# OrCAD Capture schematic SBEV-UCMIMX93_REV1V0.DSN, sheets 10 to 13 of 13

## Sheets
10 05 Gbe PHY2: size B; title: SBEV-UCMIMX93   5. Gbe PHY2; note: 17 HaYetsira Street; note: Yokneam Illit, Israel 2069208
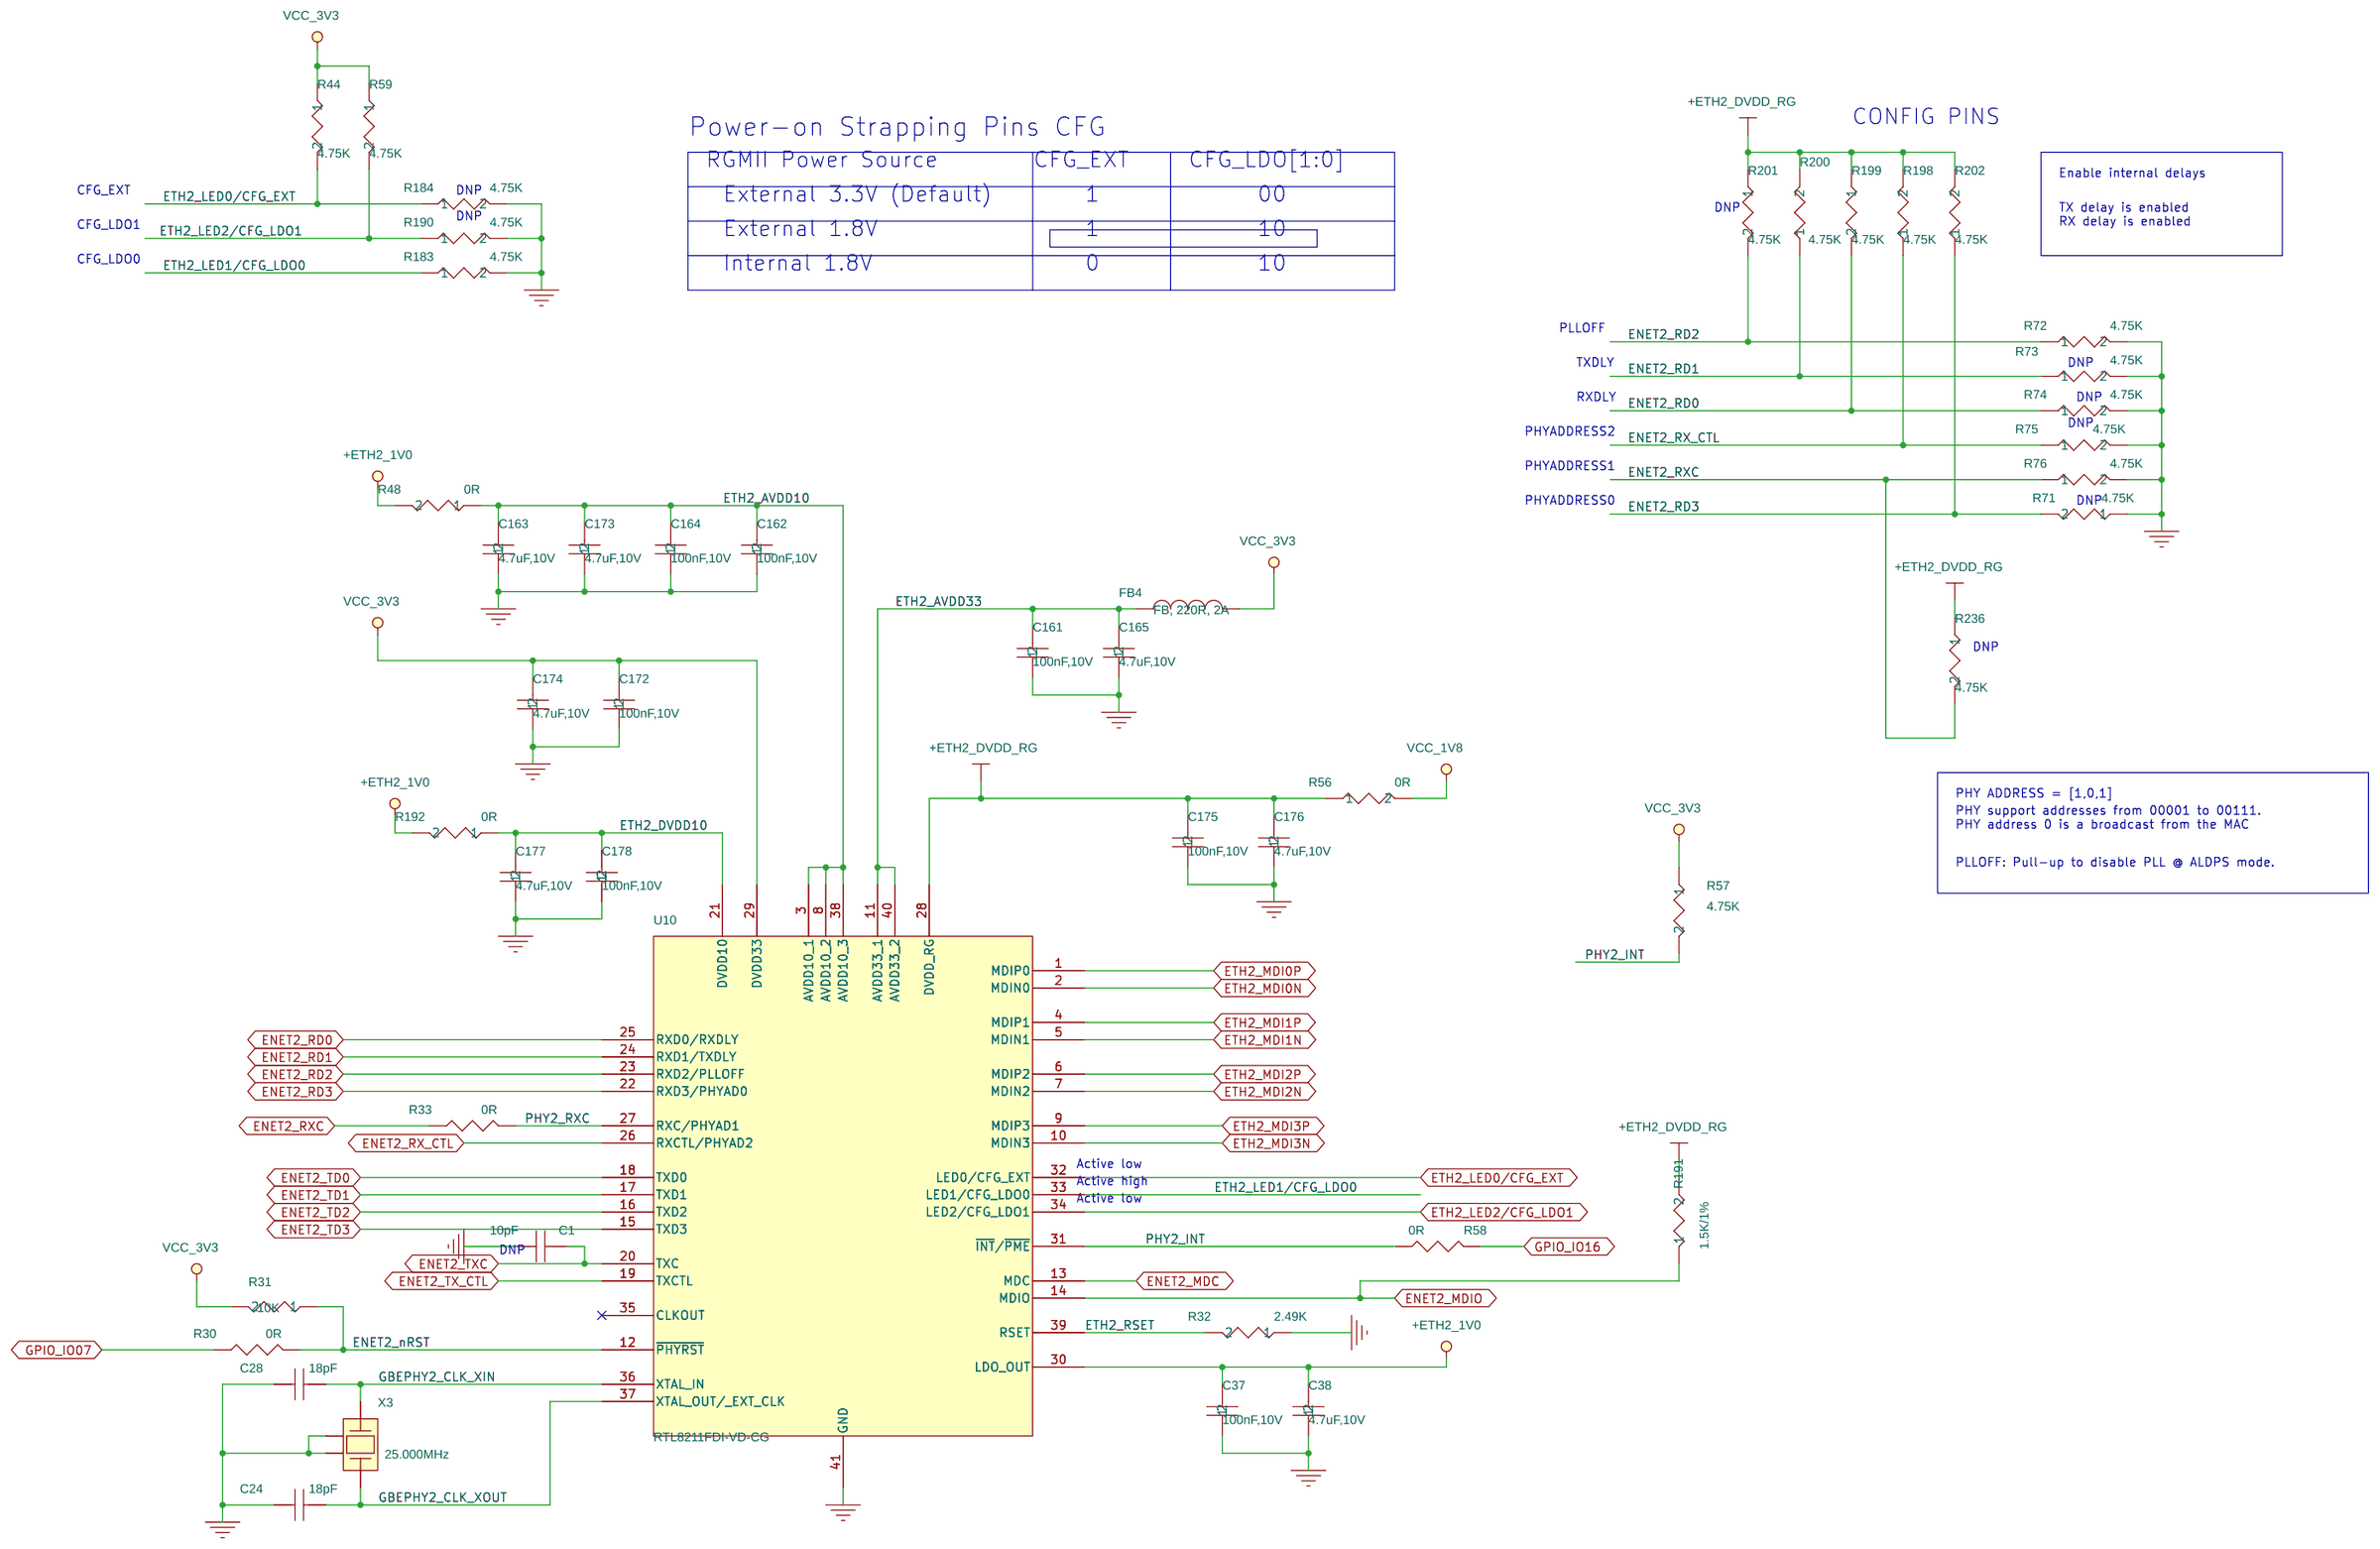
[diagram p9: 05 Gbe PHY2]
11 10 Console, SD, JTAG,miniPCI: size C; title: SBEV-UCMIMX93      10. Console, RS232, SD, miniPCIe
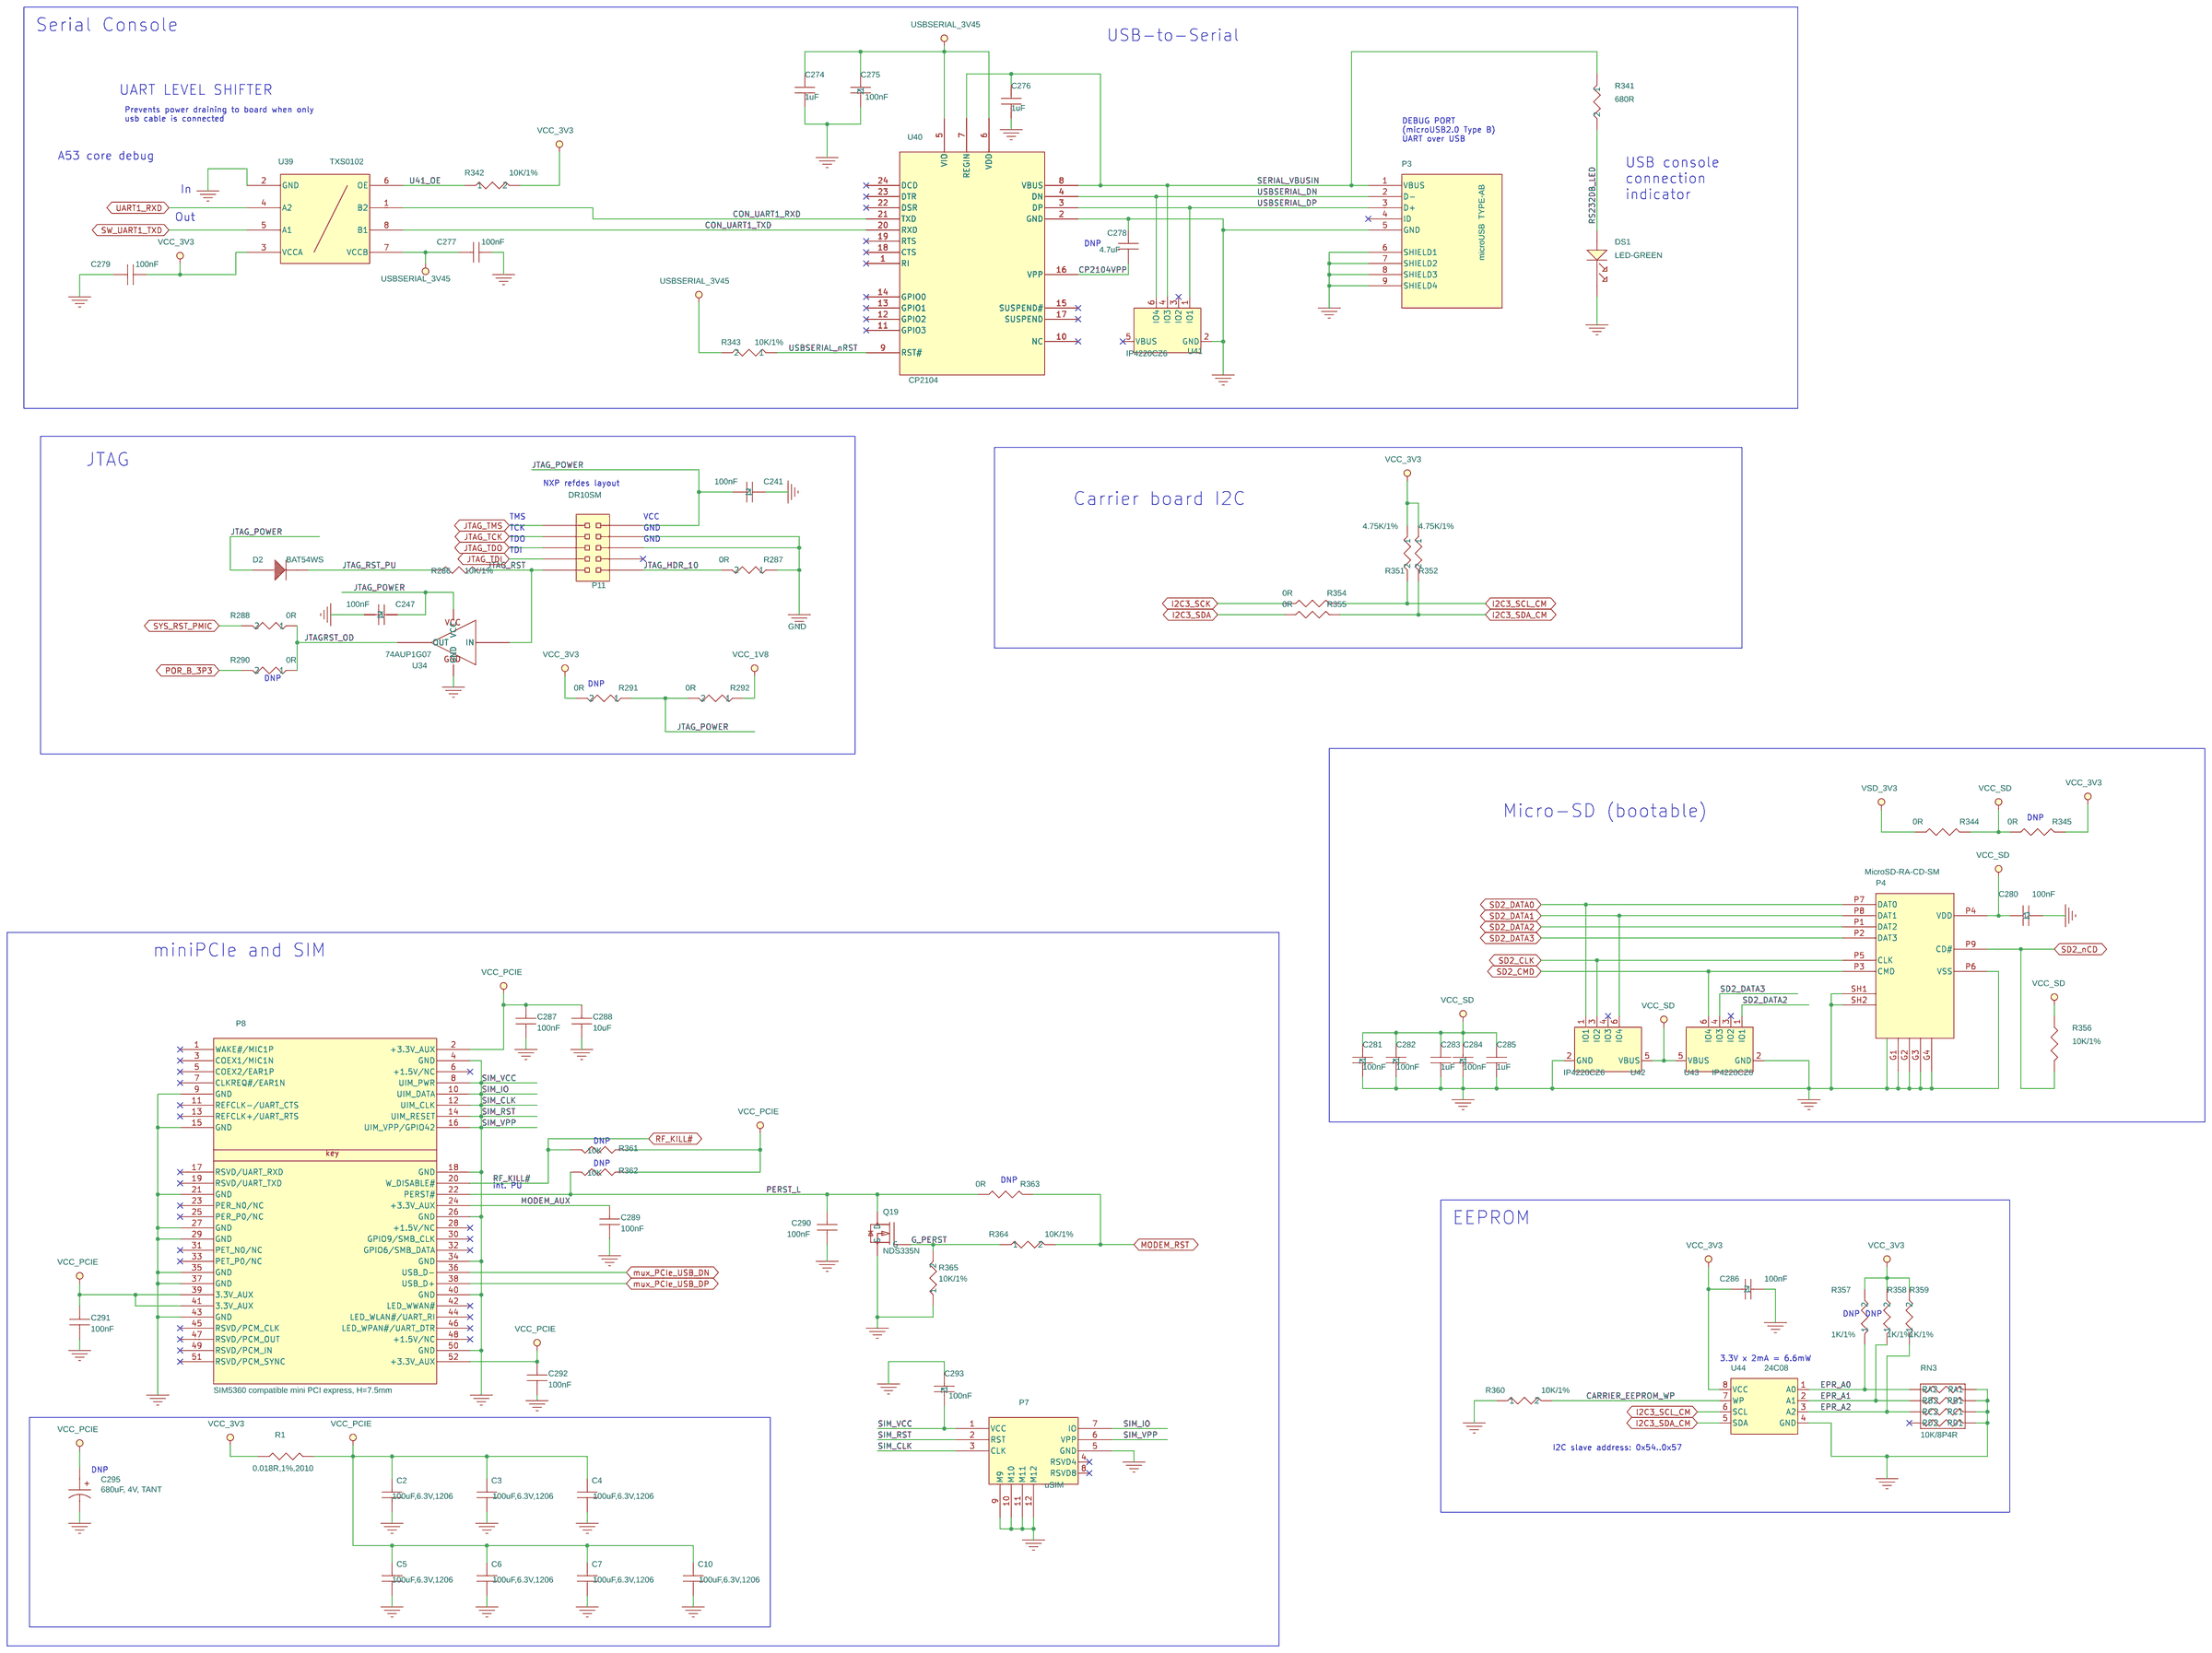
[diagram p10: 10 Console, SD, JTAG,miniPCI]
12 13 Mechanical: size B; title: SBEV-UCMIMX93      13. Mechanical
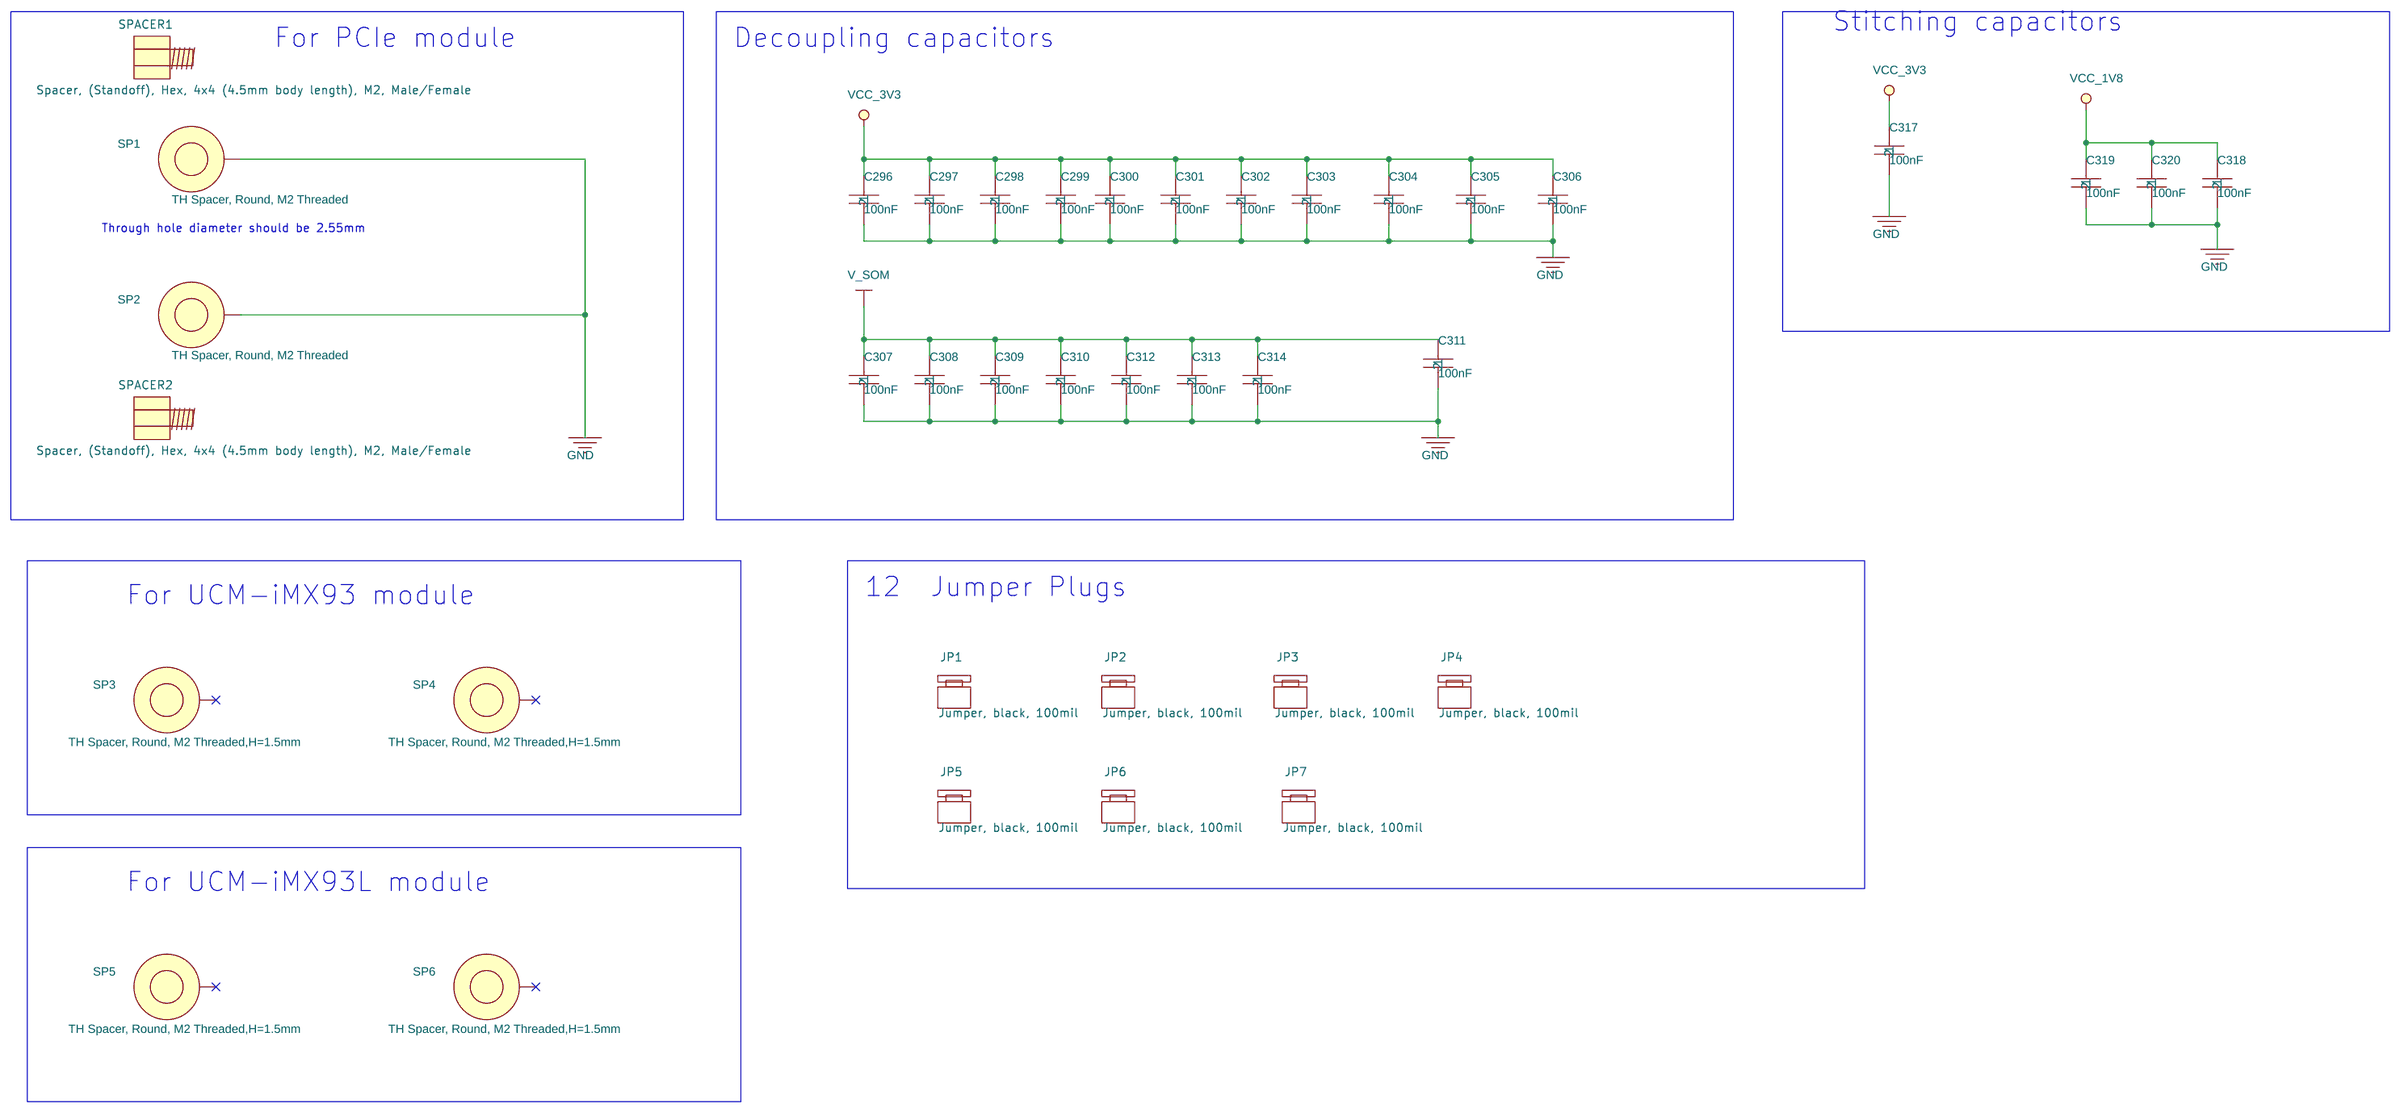
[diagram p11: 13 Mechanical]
13 12 Power: size C; title: SBEV-UCMIMX93  12. Power
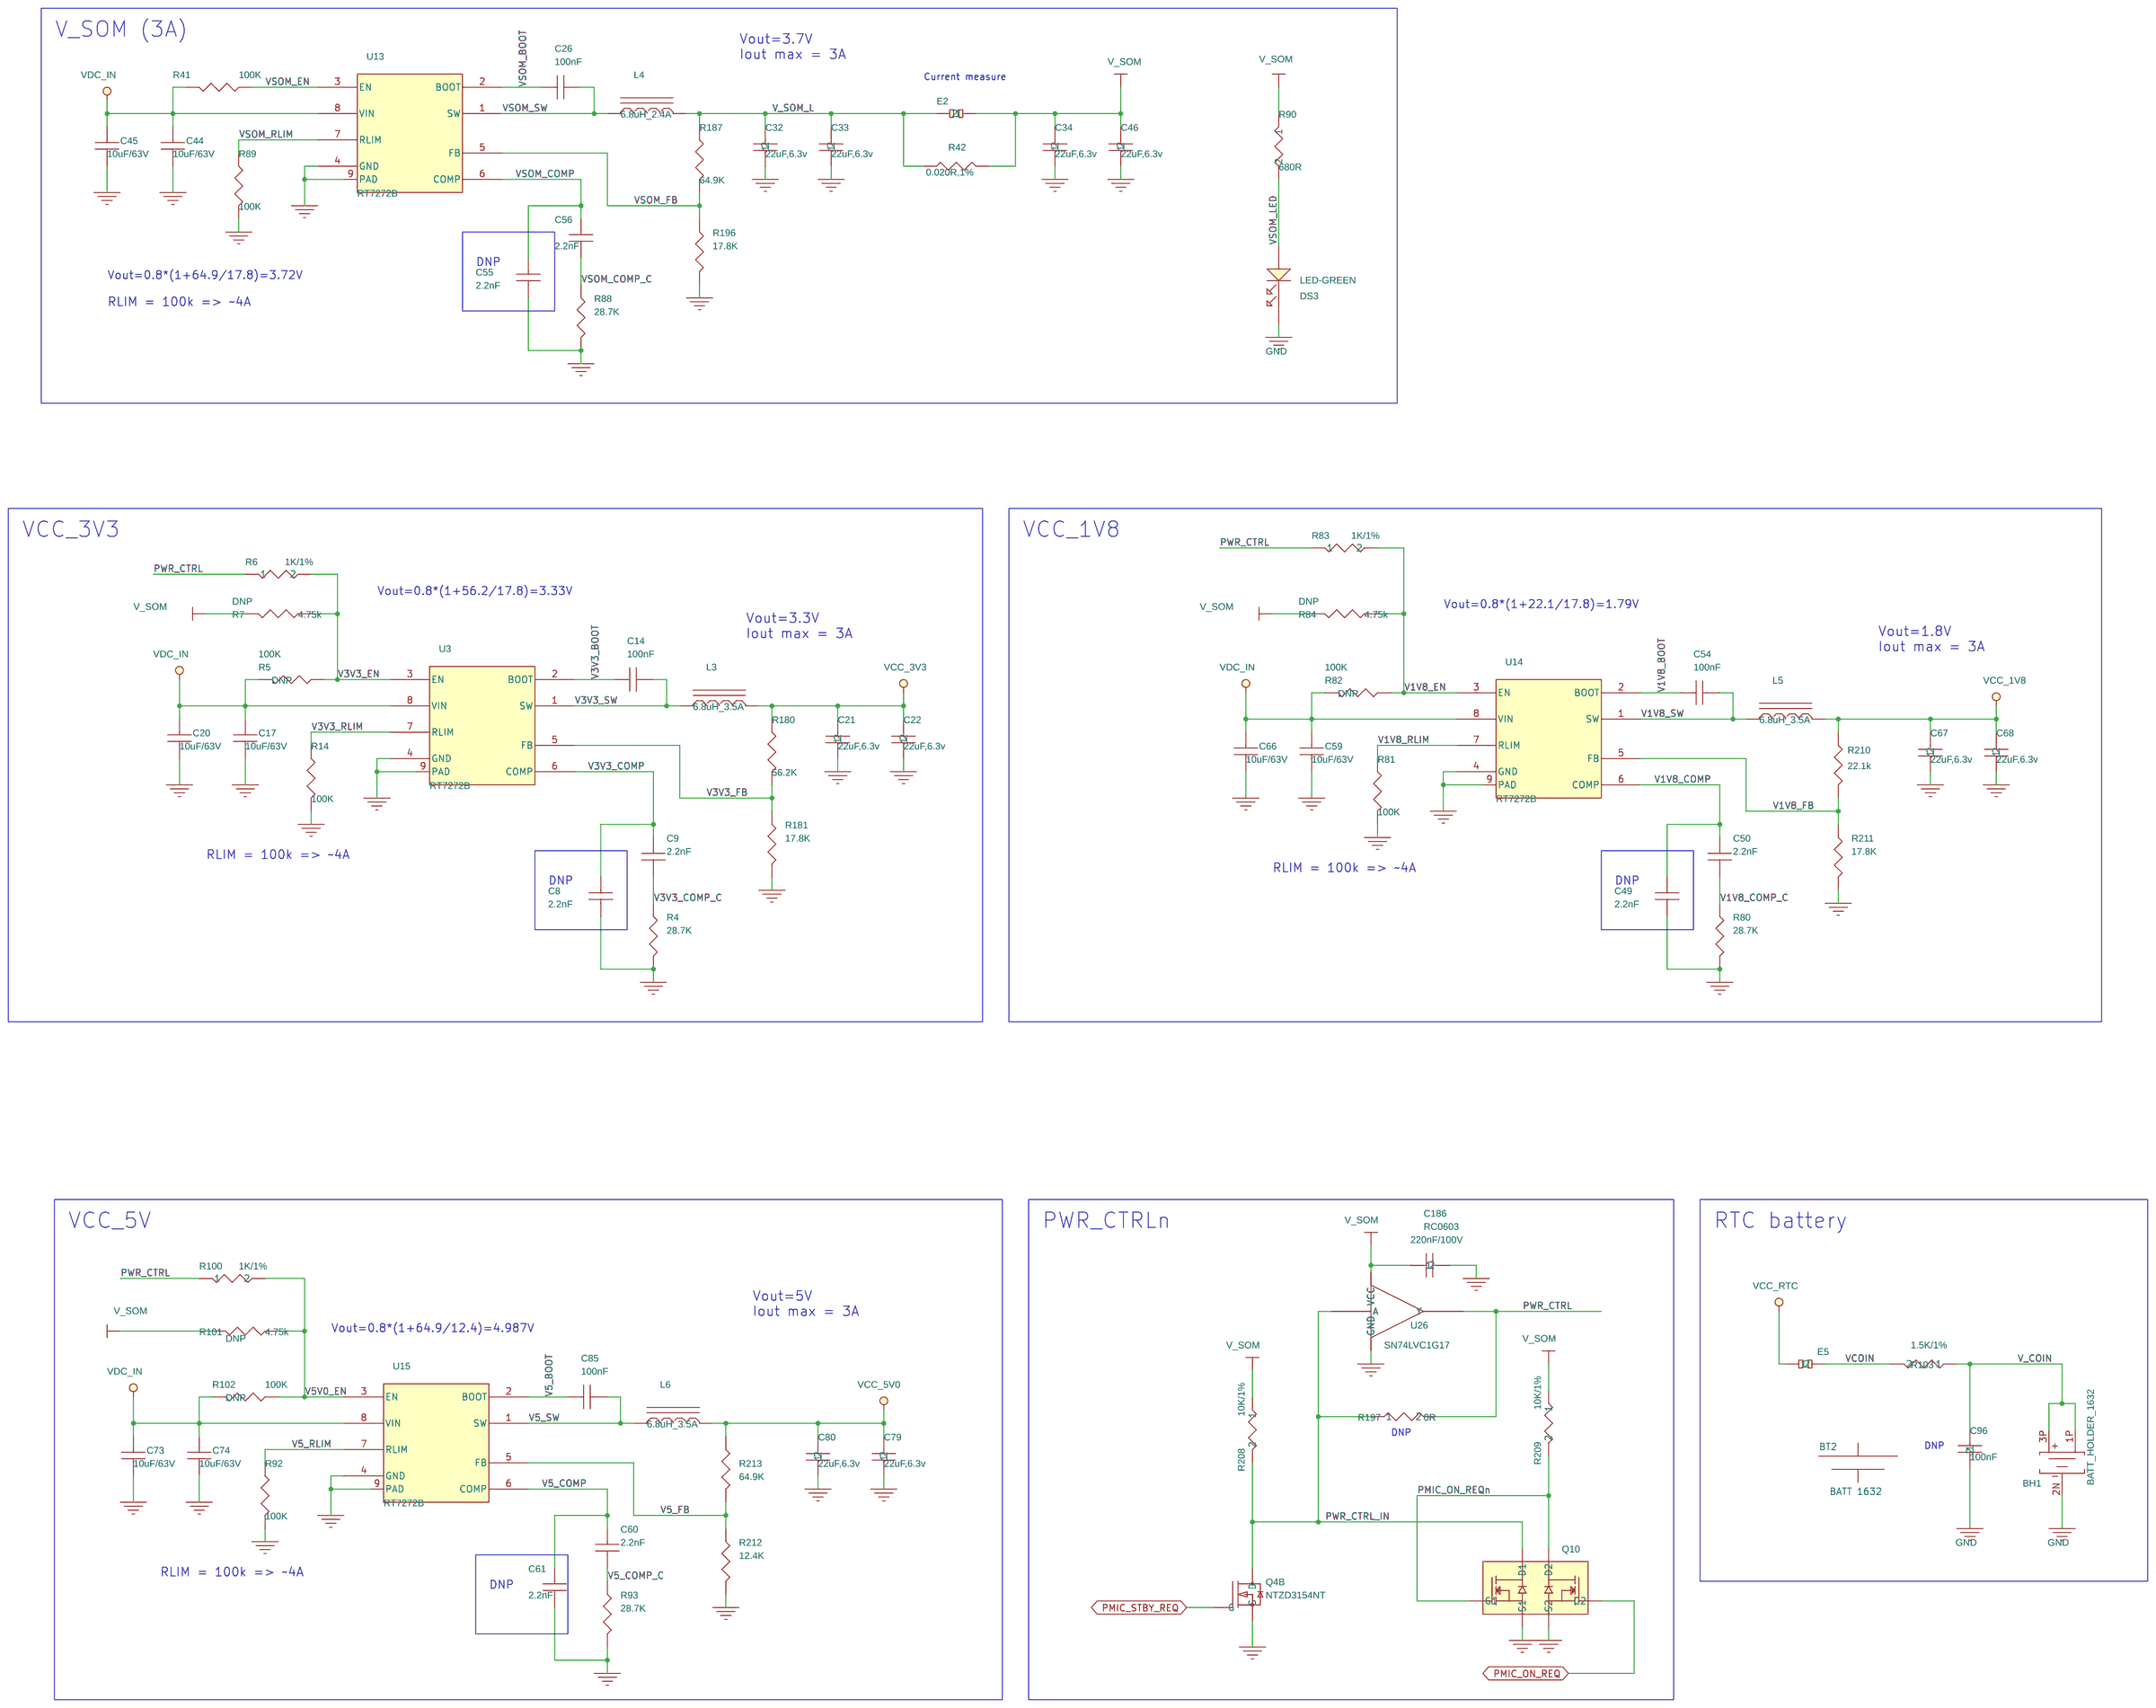
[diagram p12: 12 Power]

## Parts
sheet 05 Gbe PHY2
C1  10pF  [RC0402]
C24  18pF  [RC0402]
C28  18pF  [RC0402]
C37  100nF,10V  [RC0402]
C38  4.7uF,10V  [RC0402]
C161  100nF,10V  [RC0402]
C162  100nF,10V  [RC0402]
C163  4.7uF,10V  [RC0402]
C164  100nF,10V  [RC0402]
C165  4.7uF,10V  [RC0402]
C172  100nF,10V  [RC0402]
C173  4.7uF,10V  [RC0402]
C174  4.7uF,10V  [RC0402]
C175  100nF,10V  [RC0402]
C176  4.7uF,10V  [RC0402]
C177  4.7uF,10V  [RC0402]
C178  100nF,10V  [RC0402]
FB4  FB, 220R, 2A  [FB0402]
R30  0R  [RC0402]
R31  10K  [RC0402]
R32  2.49K  [RC0402]
R33  0R  [RC0402]
R44  4.75K  [RC0402]
R48  0R  [RC0402]
R56  0R  [RC0402]
R57  4.75K  [RC0402]
R58  0R  [RC0402]
R59  4.75K  [RC0402]
R71  4.75K  [RC0402]
R72  4.75K  [RC0402]
R73  4.75K  [RC0402]
R74  4.75K  [RC0402]
R75  4.75K  [RC0402]
R76  4.75K  [RC0402]
R183  4.75K  [RC0402]
R184  4.75K  [RC0402]
R190  4.75K  [RC0402]
R191  1.5K/1%  [RC0402]
R192  0R  [RC0402]
R198  4.75K  [RC0402]
R199  4.75K  [RC0402]
R200  4.75K  [RC0402]
R201  4.75K  [RC0402]
R202  4.75K  [RC0402]
R236  4.75K  [RC0402]
U10  RTL8211FDI-VD-CG  [qfn40_0p4_5x5mm]
X3  25.000MHz  [OSC3225]
sheet 10 Console, SD, JTAG,miniPCI
C2  100uF,6.3V,1206  [C1206]
C3  100uF,6.3V,1206  [C1206]
C4  100uF,6.3V,1206  [C1206]
C5  100uF,6.3V,1206  [C1206]
C6  100uF,6.3V,1206  [C1206]
C7  100uF,6.3V,1206  [C1206]
C10  100uF,6.3V,1206  [C1206]
C241  100nF  [RC0402]
C247  100nF  [RC0402]
C274  1uF  [RC0402]
C275  100nF  [RC0402]
C276  1uF  [RC0402]
C277  100nF  [RC0402]
C278  4.7uF  [C0603-08]
C279  100nF  [RC0402]
C280  100nF  [RC0402]
C281  100nF  [RC0402]
C282  100nF  [RC0402]
C283  1uF  [RC0402]
C284  100nF  [RC0402]
C285  1uF  [RC0402]
C286  100nF  [RC0402]
C287  100nF  [RC0402]
C288  10uF  [RC0603]
C289  100nF  [RC0402]
C290  100nF  [RC0402]
C291  100nF  [RC0402]
C292  100nF  [RC0402]
C293  100nF  [RC0402]
C295  680uF, 4V, TANT  [TANT7343]
D2  BAT54WS  [SOD-323]
DS1  LED-GREEN  [LED-1206]
P3  microUSB  TYPE-AB  [MICRO-USB-AB-RA-SM]
P4  MicroSD-RA-CD-SM  [MicroSD-RA-CD-SM]
P7  uSIM  [SKT-MicroSIM6-SM]
P8  SIM5360 compatible mini PCI express, H=7.5mm  [MINIPCIE-4]
P11  DR10SM  [2X5SMHDR]
Q19  NDS335N  [SOT23]
R1  0.018R,1%,2010  [R2010]
R286  10K/1%  [RC0402]
R287  0R  [RC0402]
R288  0R  [RC0402]
R290  0R  [RC0402]
R291  0R  [RC0402]
R292  0R  [RC0402]
R341  680R  [RC0402]
R342  10K/1%  [RC0402]
R343  10K/1%  [RC0402]
R344  0R  [RC0402]
R345  0R  [RC0402]
R351  4.75K/1%  [RC0402]
R352  4.75K/1%  [RC0402]
R354  0R  [RC0402]
R355  0R  [RC0402]
R356  10K/1%  [RC0402]
R357  1K/1%  [RC0402]
R358  1K/1%  [RC0402]
R359  1K/1%  [RC0402]
R360  10K/1%  [RC0402]
R361  10K  [RC0402]
R362  10K  [RC0402]
R363  0R  [RC0402]
R364  10K/1%  [RC0402]
R365  10K/1%  [RC0402]
RN3  10K/8P4R  [RESNET8P0805]
U34  74AUP1G07  [SC70]
U39  TXS0102  [MO-187DA-8]
U40  CP2104  [MO-220VGGD-8]
U41  IP4220CZ6  [SOT23-6L-H1]
U42  IP4220CZ6  [SOT23-6L]
U43  IP4220CZ6  [SOT23-6L]
U44  24C08  [MO-229VCED-2]
sheet 12 Power
BH1  BATT_HOLDER_1632  [BattH16mm-SM]
BT2  BATT 1632
C8  2.2nF  [RC0402]
C9  2.2nF  [RC0402]
C14  100nF  [RC0402]
C17  10uF/63V  [C1210H2_5]
C20  10uF/63V  [C1210H2_5]
C21  22uF,6.3v  [RC0603]
C22  22uF,6.3v  [RC0603]
C26  100nF  [RC0402]
C32  22uF,6.3v  [RC0603]
C33  22uF,6.3v  [RC0603]
C34  22uF,6.3v  [RC0603]
C44  10uF/63V  [C1210H2_5]
C45  10uF/63V  [C1210H2_5]
C46  22uF,6.3v  [RC0603]
C49  2.2nF  [RC0402]
C50  2.2nF  [RC0402]
C54  100nF  [RC0402]
C55  2.2nF  [RC0402]
C56  2.2nF  [RC0402]
C59  10uF/63V  [C1210H2_5]
C60  2.2nF  [RC0402]
C61  2.2nF  [RC0402]
C66  10uF/63V  [C1210H2_5]
C67  22uF,6.3v  [RC0603]
C68  22uF,6.3v  [RC0603]
C73  10uF/63V  [C1210H2_5]
C74  10uF/63V  [C1210H2_5]
C79  22uF,6.3v  [RC0603]
C80  22uF,6.3v  [RC0603]
C85  100nF  [RC0402]
C96  100nF  [RC0402]
C186  220nF/100V  [RC0603]
DS3  LED-GREEN  [LED-1206]
E2  HDR1X2  [1X2THHDR]
E5  HDR1X2  [1X2THHDR]
L3  6.8uH_3.5A  [IND6x5_5x3]
L4  6.8uH_2.4A  [IND6x5_5x3]
L5  6.8uH_3.5A  [IND6x5_5x3]
L6  6.8uH_3.5A  [IND6x5_5x3]
Q4  NTZD3154NT  [SOT-563-6]  (section B)
Q10  0.5A,20V,Vgs max 6V  [SOT-563-6]
R4  28.7K  [RC0402]
R5  100K  [RC0402]
R6  1K/1%  [RC0402]
R7  4.75k  [RC0402]
R14  100K  [RC0402]
R41  100K  [RC0402]
R42  0.020R,1%  [R1206]
R80  28.7K  [RC0402]
R81  100K  [RC0402]
R82  100K  [RC0402]
R83  1K/1%  [RC0402]
R84  4.75k  [RC0402]
R88  28.7K  [RC0402]
R89  100K  [RC0402]
R90  680R  [RC0402]
R92  100K  [RC0402]
R93  28.7K  [RC0402]
R100  1K/1%  [RC0402]
R101  4.75k  [RC0402]
R102  100K  [RC0402]
R103  1.5K/1%  [RC0402]
R180  56.2K  [RC0402]
R181  17.8K  [RC0402]
R187  64.9K  [RC0402]
R196  17.8K  [RC0402]
R197  0R  [RC0402]
R208  10K/1%  [RC0402]
R209  10K/1%  [RC0402]
R210  22.1k  [RC0402]
R211  17.8K  [RC0402]
R212  12.4K  [RC0402]
R213  64.9K  [RC0402]
U3  RT7272B  [PSOP-8-2X2]
U13  RT7272B  [PSOP-8-2X2]
U14  RT7272B  [PSOP-8-2X2]
U15  RT7272B  [PSOP-8-2X2]
U26  SN74LVC1G17
sheet 13 Mechanical
C296  100nF  [RC0402]
C297  100nF  [RC0402]
C298  100nF  [RC0402]
C299  100nF  [RC0402]
C300  100nF  [RC0402]
C301  100nF  [RC0402]
C302  100nF  [RC0402]
C303  100nF  [RC0402]
C304  100nF  [RC0402]
C305  100nF  [RC0402]
C306  100nF  [RC0402]
C307  100nF  [RC0402]
C308  100nF  [RC0402]
C309  100nF  [RC0402]
C310  100nF  [RC0402]
C311  100nF  [RC0402]
C312  100nF  [RC0402]
C313  100nF  [RC0402]
C314  100nF  [RC0402]
C317  100nF  [RC0402]
C318  100nF  [RC0402]
C319  100nF  [RC0402]
C320  100nF  [RC0402]
JP1  Jumper, black, 100mil
JP2  Jumper, black, 100mil
JP3  Jumper, black, 100mil
JP4  Jumper, black, 100mil
JP5  Jumper, black, 100mil
JP6  Jumper, black, 100mil
JP7  Jumper, black, 100mil
SP1  TH Spacer, Round, M2 Threaded  [MINIPCIE-4-Spacer]
SP2  TH Spacer, Round, M2 Threaded  [MINIPCIE-4-Spacer]
SP3  TH Spacer, Round, M2 Threaded,H=1.5mm  [SpacerM2SM]
SP4  TH Spacer, Round, M2 Threaded,H=1.5mm  [SpacerM2SM]
SP5  TH Spacer, Round, M2 Threaded,H=1.5mm  [SpacerM2SM]
SP6  TH Spacer, Round, M2 Threaded,H=1.5mm  [SpacerM2SM]
SPACER1  Spacer, (Standoff), Hex, 4x4 (4.5mm body length), M2, Male/Female  [NONE]
SPACER2  Spacer, (Standoff), Hex, 4x4 (4.5mm body length), M2, Male/Female  [NONE]

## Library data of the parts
C1 = CAP_NP: CLABCONF0: DNP; P/N: 151D10000S; Part Name: Cap., 10pF, 0402, NPO, 50V, 5% or 1%
C24 C28 = 27pF,_50V,_X7R,_10%,_0402: CLABCONF0: =SBEV-UCMIMX93; P/N: 151D18000S
C37 = 15pF,_50V,_NPO,_5%,_0402_12: CLABCONF0: =SBEV-UCMIMX93; P/N: 151B10400S
C38 = 15pF,_50V,_NPO,_5%,_0402_13: CLABCONF0: =SBEV-UCMIMX93; P/N: 151B47500S
C161 = 15pF,_50V,_NPO,_5%,_0402_7: CLABCONF0: =SBEV-UCMIMX93; P/N: 151B10400S
C162 = 15pF,_50V,_NPO,_5%,_0402_5: CLABCONF0: =SBEV-UCMIMX93; P/N: 151B10400S
C163 = 15pF,_50V,_NPO,_5%,_0402_4: CLABCONF0: =SBEV-UCMIMX93; P/N: 151B47500S
C164 = 15pF,_50V,_NPO,_5%,_0402_1: CLABCONF0: =SBEV-UCMIMX93; P/N: 151B10400S
C165 = 15pF,_50V,_NPO,_5%,_0402_9: CLABCONF0: =SBEV-UCMIMX93; P/N: 151B47500S
C172 = 15pF,_50V,_NPO,_5%,_0402_11: CLABCONF0: =SBEV-UCMIMX93; P/N: 151B10400S
C173 = 15pF,_50V,_NPO,_5%,_0402: CLABCONF0: =SBEV-UCMIMX93; P/N: 151B47500S
C174 = 15pF,_50V,_NPO,_5%,_0402_3: CLABCONF0: =SBEV-UCMIMX93; P/N: 151B47500S
C175 = 15pF,_50V,_NPO,_5%,_0402_2: CLABCONF0: =SBEV-UCMIMX93; P/N: 151B10400S
C176 = 15pF,_50V,_NPO,_5%,_0402_10: CLABCONF0: =SBEV-UCMIMX93; P/N: 151B47500S
C177 = 15pF,_50V,_NPO,_5%,_0402_6: CLABCONF0: =SBEV-UCMIMX93; P/N: 151B47500S
C178 = 15pF,_50V,_NPO,_5%,_0402_8: CLABCONF0: =SBEV-UCMIMX93; P/N: 151B10400S
FB4 = Ferrite_bead_,_120_Ohm@3A: CLABCONF0: =SBEV-UCMIMX93; P/N: 147D22101S
R30 = 0R,_0402_0_2: CLABCONF0: =SBEV-UCMIMX93
R31 = 1M_,5%,_0402_2: CLABCONF0: =SBEV-UCMIMX93; P/N: 161C10021S
R32 = 1M_,5%,_0402_1: CLABCONF0: =SBEV-UCMIMX93; P/N: 161C24911S
R33 = 0R,_0402_0: CLABCONF0: =SBEV-UCMIMX93
R44 = 4.75K,1%,0402,1_16W_16: CLABCONF0: =SBEV-UCMIMX93
R48 = 0R,_0402_1: CLABCONF0: =SBEV-UCMIMX93
R56 = 0R,_0402: CLABCONF0: =SBEV-UCMIMX93
R57 = 1M_,5%,_0402: CLABCONF0: =SBEV-UCMIMX93; P/N: 161C47511S
R58 = 0R,_0402_0_1: CLABCONF0: =SBEV-UCMIMX93
R59 = 4.75K,1%,0402,1_16W_7: CLABCONF0: =SBEV-UCMIMX93
R71 = 4.75K,1%,0402,1_16W_13: CLABCONF0: DNP
R72 = 4.75K,1%,0402,1_16W_3: CLABCONF0: =SBEV-UCMIMX93
R73 = 4.75K,1%,0402,1_16W_2: CLABCONF0: DNP
R74 = 4.75K,1%,0402,1_16W_9: CLABCONF0: DNP
R75 = 4.75K,1%,0402,1_16W_12: CLABCONF0: DNP
R76 = 4.75K,1%,0402,1_16W_1: CLABCONF0: =SBEV-UCMIMX93
R183 = 4.75K,1%,0402,1_16W: CLABCONF0: =SBEV-UCMIMX93
R184 = 4.75K,1%,0402,1_16W_8: CLABCONF0: DNP
R190 = 4.75K,1%,0402,1_16W_6: CLABCONF0: DNP
R103 R191 = 1.5K_1%,_0402: CLABCONF0: =SBEV-UCMIMX93
R192 R288 = 0R,_0402_1_1: CLABCONF0: =SBEV-UCMIMX93
R198 = 4.75K,1%,0402,1_16W_14: CLABCONF0: =SBEV-UCMIMX93
R199 = 4.75K,1%,0402,1_16W_5: CLABCONF0: =SBEV-UCMIMX93
R200 = 4.75K,1%,0402,1_16W_15: CLABCONF0: =SBEV-UCMIMX93
R201 = 4.75K,1%,0402,1_16W_4: CLABCONF0: DNP
R202 = 4.75K,1%,0402,1_16W_11: CLABCONF0: =SBEV-UCMIMX93
R236 = 4.75K,1%,0402,1_16W_10: CLABCONF0: DNP
U10 = RTL8211FDI-40P_A_0: IC XCVR ETH INTEGRATED 10/100/1000MBPS RGMII 3.3V/2.5V/1.8V QFN40; 3D_Mechanical_Footprint_File: http://fcl.am.freescale.net/ALLEGRO/step/qfn40_0p4_5x5mm.STEP; AGILE_PN: TMP-CIP-10596; CAD_APPROVED: Yes; CLABCONF0: =SBEV-UCMIMX93; HEIGHT: 0.9MM; MFG_NAME01: REALTEK SEMICONDUCTOR; P/N: 116A00640S; PRE_APN: 312-83499; Package Size: QFN40; ROHS: Yes; Temp Range: -40  °C  +85 °C
X3 = XTAL,_25.000Mhz,_3x5mm: CLABCONF0: =SBEV-UCMIMX93; P/N: 141B25603I
C2-C7 C10 = CAP_NP: CLABCONF0: =SBEV-UCMIMX93; P/N: 151B10730S; Part Name: Cap., 100uF, 6.3V, X5R, 20%, 1206, H=1.6mm
C241 = 100nF,_10V,_X7R,_10%,_0402: CLABCONF0: =SBEV-UCMIMX93
C247 = 100nF,_10V,_X7R,_10%,_0402_6: CLABCONF0: =SBEV-UCMIMX93
C274 C276 C283 C285 = 1uF,X5R,6.3V,0402: CLABCONF0: =SBEV-UCMIMX93
C275 = 100nF,_10V,_X7R,_10%,_0402_4: CLABCONF0: =SBEV-UCMIMX93
C277 C279 = 100nF,_10V,_X7R,_10%,_0402_0: CLABCONF0: =SBEV-UCMIMX93
C278 = 4.7uF,_6.3V,_X5R,_20%,_0603: CLABCONF0: DNP; P/N: 151B10610S
C280 = 100nF,_10V,_X7R,_10%,_0402_2: CLABCONF0: =SBEV-UCMIMX93
C281 = 100nF,_10V,_X7R,_10%,_0402_7: CLABCONF0: =SBEV-UCMIMX93
C282 = 100nF,_10V,_X7R,_10%,_0402_8: CLABCONF0: =SBEV-UCMIMX93
C284 = 100nF,_10V,_X7R,_10%,_0402_5: CLABCONF0: =SBEV-UCMIMX93
C286 = 100nF,_10V,_X7R,_10%,_0402_1: CLABCONF0: =SBEV-UCMIMX93
C14 C26 C54 C85 C287 C289-C292 = 100nF,_10V,_X7R,_10%,_0402_0: CLABCONF0: =SBEV-UCMIMX93; Group: LAN2
C288 = 10uF,6.3V,0603,20%X5R: CLABCONF0: =SBEV-UCMIMX93; P/N: 151B10610S
C293 = 100nF,_10V,_X7R,_10%,_0402_3: CLABCONF0: =SBEV-UCMIMX93
C295 = CAPACITOR_POL: CLABCONF0: DNP; P/N: 154A687D0S
D2 = BAT54WS_0: CLABCONF0: =SBEV-UCMIMX93
DS1 DS3 = LED-GREEN_1206_2: CLABCONF0: =SBEV-UCMIMX93
P3 = Conn.,_Micro-USB,_B-Type: CLABCONF0: =SBEV-UCMIMX93; P/N: 180K00501S
P4 = microSD_push-pull: CLABCONF0: =SBEV-UCMIMX93; P/N: 182K01300S
P7 = uSIM_SOCKET_0: CLABCONF0: =SBEV-UCMIMX93
P8 = Conn.,_Mini-PCIe,_for_SIM5360: CLABCONF0: =SBEV-UCMIMX93; P/N: 182K05203S
P11 = HDR_2x5_100MIL_SMT: CLABCONF0: =SBEV-UCMIMX93
Q19 = N-MOSFET,NDS335N,100mOhm@2.5V: CLABCONF0: =SBEV-UCMIMX93
R1 = RESISTOR: CLABCONF0: =SBEV-UCMIMX93; P/N: 161HR0181S; Part Name: Res., 0.018R, 1%, 2010, 1/2W (current sense)
R286 = 10K,1%,0402,1_16W_0_2: CLABCONF0: =SBEV-UCMIMX93
R287 = 0R,_0402_1_2: CLABCONF0: =SBEV-UCMIMX93
R290 = 0R,_0402_1: CLABCONF0: DNP
R291 = 0R,_0402_1_4: CLABCONF0: DNP
R292 = 0R,_0402_1_3: CLABCONF0: =SBEV-UCMIMX93
R90 R341 = 47K,_0402: CLABCONF0: =SBEV-UCMIMX93; P/N: 161C68001S
R209 R342 = 10K,1%,0402,1_16W: CLABCONF0: =SBEV-UCMIMX93
R343 = 10K,1%,0402,1_16W_2: CLABCONF0: =SBEV-UCMIMX93
R344 = 0R,_0402_0: CLABCONF0: =SBEV-UCMIMX93; P/N: 161C00005S
R345 = 0R,_0402_0_3: CLABCONF0: DNP; P/N: 161C00005S
R351 = 4_0.75K,1%,0402,1_16W: CLABCONF0: =SBEV-UCMIMX93
R352 = 4_0.75K,1%,0402,1_16W_1: CLABCONF0: =SBEV-UCMIMX93
R354 = 0R,_0402_0_1: CLABCONF0: =SBEV-UCMIMX93; P/N: 161C00005S
R355 = 0R,_0402_0_4: CLABCONF0: =SBEV-UCMIMX93; P/N: 161C00005S
R356 = 10K,1%,0402,1_16W_0_3: CLABCONF0: =SBEV-UCMIMX93
R357 = 1K,1%,0402,1_16W_1: CLABCONF0: DNP; Group: CAN
R358 = 1K,1%,0402,1_16W: CLABCONF0: DNP; Group: CAN
R100 R359 = 1K,1%,0402,1_16W_2: CLABCONF0: =SBEV-UCMIMX93; Group: CAN
R208 R360 = 10K,1%,0402,1_16W_1: CLABCONF0: =SBEV-UCMIMX93
R361 = 10K,1%,0402,1_16W_0: CLABCONF0: DNP; Group: Always
R362 = 10K,1%,0402,1_16W_0_1: CLABCONF0: DNP; Group: Always
R363 = 0R,_0402_0_2: CLABCONF0: DNP; P/N: 161C00005S
R364 = 10K,1%,0402,1_16W_4: CLABCONF0: =SBEV-UCMIMX93
R365 = 10K,1%,0402,1_16W_3: CLABCONF0: =SBEV-UCMIMX93
RN3 = RN,10K,8P4R@0805: CLABCONF0: =SBEV-UCMIMX93
U34 = 74AUP1G07_,_buffer_,LV: CLABCONF0: =SBEV-UCMIMX93
U39 = TXS0102_0: CLABCONF0: =SBEV-UCMIMX93; P/N: 116A01020S
U40 = CP2104_0: CLABCONF0: =SBEV-UCMIMX93; P/N: 116A00140S
U41-U43 = IP4220CZ6_0: CLABCONF0: =SBEV-UCMIMX93
U44 = 24C02,_serial_EE,_2KB,_I2C: CLABCONF0: =SBEV-UCMIMX93; P/N: 111S31000S
BH1 = BATT_HOLDER_1: CLABCONF0: =SBEV-UCMIMX93; P/N: 190Z00300S
BT2 = BATT_2032: CLABCONF0: =SBEV-UCMIMX93; P/N: 210C30006
C8 = 2.2nF,_50V,_X7R,_10%,_0402_6: CLABCONF0: DNP
C9 = 2.2nF,_50V,_X7R,_10%,_0402_3: CLABCONF0: =SBEV-UCMIMX93
C17 C20 C59 C66 C73 C74 = 22uF_25V: CLABCONF0: =SBEV-UCMIMX93; P/N: 151E10680S
C21 = 100nF,_10V,_X7R,_10%,_0402_7: CLABCONF0: =SBEV-UCMIMX93; P/N: 151B22610S
C22 = 100nF,_10V,_X7R,_10%,_0402_11: CLABCONF0: =SBEV-UCMIMX93; P/N: 151B22610S
C32 = 100nF,_10V,_X7R,_10%,_0402_2: CLABCONF0: =SBEV-UCMIMX93; P/N: 151B22610S
C33 = 100nF,_10V,_X7R,_10%,_0402_9: CLABCONF0: =SBEV-UCMIMX93; P/N: 151B22610S
C34 = 100nF,_10V,_X7R,_10%,_0402_5: CLABCONF0: =SBEV-UCMIMX93; P/N: 151B22610S
C44 C45 = 22uF_25V: CLABCONF0: =SBEV-UCMIMX93; P/N: 151D10630S
C46 = 100nF,_10V,_X7R,_10%,_0402_6: CLABCONF0: =SBEV-UCMIMX93; P/N: 151B22610S
C49 = 2.2nF,_50V,_X7R,_10%,_0402_1: CLABCONF0: DNP
C50 = 2.2nF,_50V,_X7R,_10%,_0402_5: CLABCONF0: =SBEV-UCMIMX93
C55 = 2.2nF,_50V,_X7R,_10%,_0402_4: CLABCONF0: DNP
C56 = 2.2nF,_50V,_X7R,_10%,_0402_7: CLABCONF0: =SBEV-UCMIMX93
C60 = 2.2nF,_50V,_X7R,_10%,_0402_2: CLABCONF0: =SBEV-UCMIMX93
C61 = 2.2nF,_50V,_X7R,_10%,_0402: CLABCONF0: DNP
C67 = 100nF,_10V,_X7R,_10%,_0402_8: CLABCONF0: =SBEV-UCMIMX93; P/N: 151B22610S
C68 = 100nF,_10V,_X7R,_10%,_0402: CLABCONF0: =SBEV-UCMIMX93; P/N: 151B22610S
C79 = 100nF,_10V,_X7R,_10%,_0402_3: CLABCONF0: =SBEV-UCMIMX93; P/N: 151B22610S
C80 = 100nF,_10V,_X7R,_10%,_0402_1: CLABCONF0: =SBEV-UCMIMX93; P/N: 151B22610S
C96 = 100nF,_10V,_X7R,_10%,_0402_4: CLABCONF0: DNP; P/N: 151B10400S
C186 = 100nF,_10V,_X7R,_10%,_0402_10: CLABCONF0: =SBEV-UCMIMX93; P/N: 151E22410S
E2 = HDR_1x2_100MIL_TH_JUMPER: CLABCONF0: =SBEV-UCMIMX93
E5 = HDR_1x2_100MIL_TH_JUMPER_1: CLABCONF0: =SBEV-UCMIMX93
L3 L5 L6 = IND_6.8uH_3.5A: CLABCONF0: =SBEV-UCMIMX93; P/N: 147A6R802S
L4 = IND_6.8uH_3.5A: CLABCONF0: =SBEV-UCMIMX93; P/N: 147A6R804S
Q4 = N-MOSFET_Dual: CLABCONF0: =SBEV-UCMIMX93; P/N: 131D31540S
Q10 = DUAL_N-MOSFET,_0.5A_20V: CLABCONF0: =SBEV-UCMIMX93
R4 R80 R88 R93 = 40.2k_1%: CLABCONF0: =SBEV-UCMIMX93; P/N: 161C28721S
R5 R82 R102 = 100K,_0402_0: CLABCONF0: DNP
R6 = 1K,1%,0402,1_16W_1: CLABCONF0: =SBEV-UCMIMX93; Group: CAN
R7 R84 R101 = 100K,_0402_0: CLABCONF0: DNP; P/N: 161C47511S
R14 R41 R81 R89 R92 = 100K,_0402_0: CLABCONF0: =SBEV-UCMIMX93
R42 = RESISTOR: CLABCONF0: =SBEV-UCMIMX93; P/N: 161G02011S; Part Name: Res., 0.020R, 1%, 1206, 1/2W (Current sense)
R83 = 1K,1%,0402,1_16W: CLABCONF0: =SBEV-UCMIMX93; Group: CAN
R180 = 10.5K_1%,0402: CLABCONF0: =SBEV-UCMIMX93; P/N: 161C56221S
R181 R196 R211 = 2.37K_1%,_0402: CLABCONF0: =SBEV-UCMIMX93; P/N: 161C17821S
R187 R213 = 10.5K_1%,0402: CLABCONF0: =SBEV-UCMIMX93; P/N: 161C64921S
R197 = 0R,_0402: CLABCONF0: DNP
R210 = RESISTOR: CLABCONF0: =SBEV-UCMIMX93; P/N: 161C22121S
R212 = 2.37K_1%,_0402: CLABCONF0: =SBEV-UCMIMX93; P/N: 161C12421S
U3 U13-U15 = RT7272B,Converter,3A,36V: CLABCONF0: =SBEV-UCMIMX93; P/N: 123V30000S
U26 = SN74LVC1G17: CLABCONF0: =SBEV-UCMIMX93; P/N: 106D90000S
C296 = 100nF,_10V,_X7R,_10%,_0402: CLABCONF0: =SBEV-UCMIMX93; P/N: 151B10400S
C297 = 100nF,_10V,_X7R,_10%,_0402_12: CLABCONF0: =SBEV-UCMIMX93; P/N: 151B10400S
C298 = 100nF,_10V,_X7R,_10%,_0402_13: CLABCONF0: =SBEV-UCMIMX93; P/N: 151B10400S
C299 = 100nF,_10V,_X7R,_10%,_0402_22: CLABCONF0: =SBEV-UCMIMX93; P/N: 151B10400S
C300 = 100nF,_10V,_X7R,_10%,_0402_4: CLABCONF0: =SBEV-UCMIMX93; P/N: 151B10400S
C301 = 100nF,_10V,_X7R,_10%,_0402_15: CLABCONF0: =SBEV-UCMIMX93; P/N: 151B10400S
C302 = 100nF,_10V,_X7R,_10%,_0402_16: CLABCONF0: =SBEV-UCMIMX93; P/N: 151B10400S
C303 = 100nF,_10V,_X7R,_10%,_0402_2: CLABCONF0: =SBEV-UCMIMX93; P/N: 151B10400S
C304 = 100nF,_10V,_X7R,_10%,_0402_14: CLABCONF0: =SBEV-UCMIMX93; P/N: 151B10400S
C305 = 100nF,_10V,_X7R,_10%,_0402_20: CLABCONF0: =SBEV-UCMIMX93; P/N: 151B10400S
C306 = 100nF,_10V,_X7R,_10%,_0402_19: CLABCONF0: =SBEV-UCMIMX93; P/N: 151B10400S
C307 = 100nF,_10V,_X7R,_10%,_0402_8: CLABCONF0: =SBEV-UCMIMX93; P/N: 151B10400S
C308 = 100nF,_10V,_X7R,_10%,_0402_18: CLABCONF0: =SBEV-UCMIMX93; P/N: 151B10400S
C309 = 100nF,_10V,_X7R,_10%,_0402_11: CLABCONF0: =SBEV-UCMIMX93; P/N: 151B10400S
C310 = 100nF,_10V,_X7R,_10%,_0402_3: CLABCONF0: =SBEV-UCMIMX93; P/N: 151B10400S
C311 = 100nF,_10V,_X7R,_10%,_0402_6: CLABCONF0: =SBEV-UCMIMX93; P/N: 151B10400S
C312 = 100nF,_10V,_X7R,_10%,_0402_21: CLABCONF0: =SBEV-UCMIMX93; P/N: 151B10400S
C313 = 100nF,_10V,_X7R,_10%,_0402_9: CLABCONF0: =SBEV-UCMIMX93; P/N: 151B10400S
C314 = 100nF,_10V,_X7R,_10%,_0402_10: CLABCONF0: =SBEV-UCMIMX93; P/N: 151B10400S
C317 = 100nF,_10V,_X7R,_10%,_0402_1: CLABCONF0: =SBEV-UCMIMX93; P/N: 151B10400S
C318 = 100nF,_10V,_X7R,_10%,_0402_7: CLABCONF0: =SBEV-UCMIMX93; P/N: 151B10400S
C319 = 100nF,_10V,_X7R,_10%,_0402_17: CLABCONF0: =SBEV-UCMIMX93; P/N: 151B10400S
C320 = 100nF,_10V,_X7R,_10%,_0402_5: CLABCONF0: =SBEV-UCMIMX93; P/N: 151B10400S
JP1-JP7 = Jumper,_black,_100mil: CLABCONF0: =SBEV-UCMIMX93
SP1 SP2 = SMT_SPACER_M2x3_2: CLABCONF0: =SBEV-UCMIMX93; P/N: 383B52531S
SP3-SP6 = SMT_SPACER_M2x3_2: CLABCONF0: =SBEV-UCMIMX93; P/N: 383B52500S
SPACER1 SPACER2 = Hexagonal_Standoff_0: CLABCONF0: =SBEV-UCMIMX93; P/N: 206C10160

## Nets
GND: BH1.2N(-) C1.1 C2.2 C3.2 C4.2 C5.2 C6.2 C7.2 C8.2 C10.2 C17.2 C20.2 C21.1 C22.1 C24.1 C28.1 C32.1 C33.1 C34.1 C37.1 C38.1 C44.2 C45.2 C46.1 C49.2 C55.2 C59.2 C61.2 C66.2 C67.1 C68.1 C73.2 C74.2 C79.1 C80.1 C96.2 C161.1 C162.1 C163.1 C164.1 C165.1 C172.1 C173.1 C174.1 C175.1 C176.1 C177.1 C178.1 C186.2 C241.1 C247.2 C274.2 C275.2 C276.2 C277.1 C278.2 C279.2 C280.2 C281.2 C282.2 C283.2 C284.2 C285.2 C286.1 C287.2 C288.2 C289.2 C290.2 C291.2 C292.2 C293.1 C295.2 C296.2 C297.2 C298.2 C299.2 C300.2 C301.2 C302.2 C303.2 C304.2 C305.2 C306.2 C307.2 C308.2 C309.2 C310.2 C311.2 C312.2 C313.2 C314.2 C317.2 C318.2 C319.2 C320.2 DS1.CATHODE DS3.CATHODE P3.5(GND) P3.6(SHIELD1) P3.7(SHIELD2) P3.8(SHIELD3) P3.9(SHIELD4) P4.G1 P4.G2 P4.G3 P4.G4 P4.P6(VSS) P4.SH1 P4.SH2 P7.5(GND) P7.9(M9) P7.10(M10) P7.11(M11) P7.12(M12) P8.4(GND) P8.9(GND) P8.15(GND) P8.18(GND) P8.21(GND) P8.26(GND) P8.27(GND) P8.29(GND) P8.34(GND) P8.35(GND) P8.37(GND) P8.40(GND) P8.43(GND) P8.50(GND) P11.4 P11.6 Q4.4(S) Q10.1(S1) Q10.4(S2) Q19.2(S) R4.2 R14.2 R32.1 R71.1 R72.2 R73.2 R74.2 R75.2 R76.2 R80.2 R81.2 R88.2 R89.2 R92.2 R93.2 R181.2 R183.2 R184.2 R190.2 R196.2 R211.2 R212.2 R287.1 R360.1 R365.1 RN3.1(RA1) RN3.2(RB1) RN3.3(RC1) RN3.4(RD1) SP1.1 SP2.1 U3.4(GND) U3.9(PAD) U10.41(GND) U13.4(GND) U13.9(PAD) U14.4(GND) U14.9(PAD) U15.4(GND) U15.9(PAD) U26.3(GND) U34.3(GND) U39.2(GND) U40.2(GND) U41.2(GND) U42.2(GND) U43.2(GND) U44.4(GND) X3.2 X3.4 ; also on sheet 2 3 4 5 6 7 8 9
V1V8_BOOT: C54.1 U14.2(BOOT)
V1V8_COMP: C49.1 C50.1 U14.6(COMP)
V1V8_COMP_C: C50.2 R80.1
V1V8_EN: R82.1 R83.2 R84.1 U14.3(EN)
V1V8_FB: R210.2 R211.1 U14.5(FB)
V1V8_RLIM: R81.1 U14.7(RLIM)
V1V8_SW: C54.2 L5.1 U14.1(SW)
V3V3_BOOT: C14.1 U3.2(BOOT)
V3V3_COMP: C8.1 C9.1 U3.6(COMP)
V3V3_COMP_C: C9.2 R4.1
V3V3_EN: R5.1 R6.2 R7.1 U3.3(EN)
V3V3_FB: R180.2 R181.1 U3.5(FB)
V3V3_RLIM: R14.1 U3.7(RLIM)
V3V3_SW: C14.2 L3.1 U3.1(SW)
V5_BOOT: C85.1 U15.2(BOOT)
V5_COMP: C60.1 C61.1 U15.6(COMP)
V5_COMP_C: C60.2 R93.1
V5_FB: R212.1 R213.2 U15.5(FB)
V5_RLIM: R92.1 U15.7(RLIM)
V5_SW: C85.2 L6.1 U15.1(SW)
V5V0_EN: R100.2 R101.1 R102.1 U15.3(EN)
VCC_1V8: C67.2 C68.2 C318.1 C319.1 C320.1 L5.2 R56.2 R210.1 R292.1 ; also on sheet 3 6 7
VCC_3V3: C21.2 C22.2 C172.2 C174.2 C279.1 C286.2 C296.1 C297.1 C298.1 C299.1 C300.1 C301.1 C302.1 C303.1 C304.1 C305.1 C306.1 C317.1 FB4.2 L3.2 R1.1 R31.2 R44.1 R57.1 R59.1 R180.1 R291.2 R342.2 R345.1 R351.1 R352.1 R357.2 R358.2 R359.2 U10.29(DVDD33) U39.3(VCCA) U44.8(VCC) ; also on sheet 2 3 4 5 6 7 8 9
VCC_5V0: C79.2 C80.2 L6.2 R213.1 ; also on sheet 3 5 6 7 9
VCC_PCIE: C2.1 C3.1 C4.1 C5.1 C6.1 C7.1 C10.1 C287.1 C288.1 C291.1 C292.1 C295.1 P8.2(+3.3V_AUX) P8.39(3.3V_AUX) P8.41(3.3V_AUX) P8.52(+3.3V_AUX) R1.2 R361.1 R362.1
VCC_RTC: E5.1 ; also on sheet 2
VCC_SD: C280.1 C281.1 C282.1 C283.1 C284.1 C285.1 P4.P4(VDD) R344.1 R345.2 R356.1 U42.5(VBUS) U43.5(VBUS)
+ETH2_1V0: C37.2 C38.2 R48.2 R192.2 U10.30(LDO_OUT)
+ETH2_DVDD_RG: C175.2 C176.2 R56.1 R191.2 R198.2 R199.1 R200.2 R201.1 R202.2 R236.1 U10.28(DVDD_RG)
CARRIER_EEPROM_WP: R360.2 U44.7(WP)
CON_UART1_RXD: U39.1(B2) U40.21(TXD)
CON_UART1_TXD: U39.8(B1) U40.20(RXD)
CP2104VPP: C278.1 U40.16(VPP)
ENET2_MDC: U10.13(MDC) ; also on sheet 2
ENET2_MDIO: R191.1 U10.14(MDIO) ; also on sheet 2
ENET2_nRST: R30.1 R31.1 U10.12(~{PHYRST})
ENET2_RD0: R74.1 R199.2 U10.25(RXD0/RXDLY) ; also on sheet 2
ENET2_RD1: R73.1 R200.1 U10.24(RXD1/TXDLY) ; also on sheet 2
ENET2_RD2: R72.1 R201.2 U10.23(RXD2/PLLOFF) ; also on sheet 2
ENET2_RD3: R71.2 R202.1 U10.22(RXD3/PHYAD0) ; also on sheet 2
ENET2_RX_CTL: R75.1 R198.1 U10.26(RXCTL/PHYAD2) ; also on sheet 2
ENET2_RXC: R33.2 R76.1 R236.2 ; also on sheet 2
ENET2_TD0: U10.18(TXD0) ; also on sheet 2
ENET2_TD1: U10.17(TXD1) ; also on sheet 2
ENET2_TD2: U10.16(TXD2) ; also on sheet 2
ENET2_TD3: U10.15(TXD3) ; also on sheet 2
ENET2_TX_CTL: U10.19(TXCTL) ; also on sheet 2
ENET2_TXC: C1.2 U10.20(TXC) ; also on sheet 2
EPR_A0: R357.1 RN3.8(RA2) U44.1(A0)
EPR_A1: R358.1 RN3.7(RB2) U44.2(A1)
EPR_A2: R359.1 RN3.6(RC2) U44.3(A2)
ETH2_AVDD10: C162.2 C163.2 C164.2 C173.2 R48.1 U10.3(AVDD10_1) U10.8(AVDD10_2) U10.38(AVDD10_3)
ETH2_AVDD33: C161.2 C165.2 FB4.1 U10.11(AVDD33_1) U10.40(AVDD33_2)
ETH2_DVDD10: C177.2 C178.2 R192.1 U10.21(DVDD10)
ETH2_LED0/CFG_EXT: R44.2 R184.1 U10.32(LED0/CFG_EXT) ; also on sheet 4
ETH2_LED1/CFG_LDO0: R183.1 U10.33(LED1/CFG_LDO0)
ETH2_LED2/CFG_LDO1: R59.2 R190.1 U10.34(LED2/CFG_LDO1) ; also on sheet 4
ETH2_MDI0N: U10.2(MDIN0) ; also on sheet 4
ETH2_MDI0P: U10.1(MDIP0) ; also on sheet 4
ETH2_MDI1N: U10.5(MDIN1) ; also on sheet 4
ETH2_MDI1P: U10.4(MDIP1) ; also on sheet 4
ETH2_MDI2N: U10.7(MDIN2) ; also on sheet 4
ETH2_MDI2P: U10.6(MDIP2) ; also on sheet 4
ETH2_MDI3N: U10.10(MDIN3) ; also on sheet 4
ETH2_MDI3P: U10.9(MDIP3) ; also on sheet 4
ETH2_RSET: R32.2 U10.39(RSET)
G_PERST: Q19.1(G) R364.1 R365.2
GBEPHY2_CLK_XIN: C28.2 U10.36(XTAL_IN) X3.3
GBEPHY2_CLK_XOUT: C24.2 U10.37(XTAL_OUT/_EXT_CLK) X3.1
GPIO_IO07: R30.2 ; also on sheet 2
GPIO_IO16: R58.2 ; also on sheet 2
I2C3_SCK: R354.2 ; also on sheet 2
I2C3_SCL_CM: R351.2 R354.1 U44.6(SCL) ; also on sheet 6 7 9
I2C3_SDA: R355.2 ; also on sheet 2
I2C3_SDA_CM: R352.2 R355.1 U44.5(SDA) ; also on sheet 6 7 9
JTAG_HDR_10: P11.10 R287.2
JTAG_POWER: C241.2 C247.1 D2.ANODE P11.2 R291.1 R292.2 U34.5(VCC)
JTAG_RST: P11.9 R286.2 U34.2(IN)
JTAG_RST_PU: D2.CATHODE R286.1
JTAG_TCK: P11.3 ; also on sheet 2
JTAG_TDI: P11.7 ; also on sheet 2
JTAG_TDO: P11.5 ; also on sheet 2
JTAG_TMS: P11.1 ; also on sheet 2
JTAGRST_OD: R288.1 R290.1 U34.4(OUT)
MODEM_AUX: C289.1 P8.24(+3.3V_AUX)
MODEM_RST: R363.1 R364.2 ; also on sheet 6
mux_PCIe_USB_DN: P8.36(USB_D-) ; also on sheet 5
mux_PCIe_USB_DP: P8.38(USB_D+) ; also on sheet 5
PERST_L: C290.1 P8.22(PERST#) Q19.3(D) R362.2 R363.2
PHY2_INT: R57.2 R58.1 U10.31(~{INT}/~{PME})
PHY2_RXC: R33.1 U10.27(RXC/PHYAD1)
PMIC_ON_REQ: Q10.5(G2) ; also on sheet 2 6
PMIC_ON_REQn: Q10.2(G1) Q10.3(D2) R209.2
PMIC_STBY_REQ: Q4.5(G) ; also on sheet 2 6
POR_B_3P3: R290.2 ; also on sheet 2 6
PWR_CTRL: R6.1 R83.1 R100.1 R197.2 U26.4(Y)
PWR_CTRL_IN: Q4.3(D) Q10.6(D1) R197.1 R208.2 U26.2(A)
RF_KILL#: P8.20(W_DISABLE#) R361.2 ; also on sheet 6
RS232DB_LED: DS1.ANODE R341.2
SD2_CLK: P4.P5(CLK) U42.3(IO2) ; also on sheet 2
SD2_CMD: P4.P3(CMD) U43.6(IO4) ; also on sheet 2
SD2_DATA0: P4.P7(DAT0) U42.1(IO1) ; also on sheet 2
SD2_DATA1: P4.P8(DAT1) U42.6(IO4) ; also on sheet 2
SD2_DATA2: P4.P1(DAT2) U43.1(IO1) ; also on sheet 2
SD2_DATA3: P4.P2(DAT3) U43.4(IO3) ; also on sheet 2
SD2_nCD: P4.P9(CD#) R356.2 ; also on sheet 2
SERIAL_VBUSIN: C276.1 P3.1(VBUS) R341.1 U40.7(REGIN) U40.8(VBUS) U41.4(IO3)
SIM_CLK: P7.3(CLK) P8.12(UIM_CLK)
SIM_IO: P7.7(IO) P8.10(UIM_DATA)
SIM_RST: P7.2(RST) P8.14(UIM_RESET)
SIM_VCC: C293.2 P7.1(VCC) P8.8(UIM_PWR)
SIM_VPP: P7.6(VPP) P8.16(UIM_VPP/GPIO42)
SW_UART1_TXD: U39.5(A1) ; also on sheet 2
SYS_RST_PMIC: R288.2 ; also on sheet 2 6
U41_OE: R342.1 U39.6(OE)
UART1_RXD: U39.4(A2) ; also on sheet 2
USBSERIAL_3V45: C274.1 C275.1 C277.2 R343.2 U39.7(VCCB) U40.5(VIO) U40.6(VDD)
USBSERIAL_DN: P3.2(D-) U40.4(DN) U41.6(IO4)
USBSERIAL_DP: P3.3(D+) U40.3(DP) U41.1(IO1)
USBSERIAL_nRST: R343.1 U40.9(RST#)
V_COIN: BH1.1P(+) BH1.3P(+) C96.1 R103.1
V_SOM: C34.2 C46.2 C186.1 C307.1 C308.1 C309.1 C310.1 C311.1 C312.1 C313.1 C314.1 E2.1 R7.2 R42.2 R84.2 R90.1 R101.2 R208.1 R209.1 U26.5(VCC) ; also on sheet 2 3
V_SOM_L: C32.2 C33.2 E2.2 L4.2 R42.1 R187.1
VCOIN: E5.2 R103.2
VDC_IN: C17.1 C20.1 C44.1 C45.1 C59.1 C66.1 C73.1 C74.1 R5.2 R41.2 R82.2 R102.2 U3.8(VIN) U13.8(VIN) U14.8(VIN) U15.8(VIN) ; also on sheet 3
VSD_3V3: R344.2 ; also on sheet 2
VSOM_BOOT: C26.1 U13.2(BOOT)
VSOM_COMP: C55.1 C56.1 U13.6(COMP)
VSOM_COMP_C: C56.2 R88.1
VSOM_EN: R41.1 U13.3(EN)
VSOM_FB: R187.2 R196.1 U13.5(FB)
VSOM_LED: DS3.ANODE R90.2
VSOM_RLIM: R89.1 U13.7(RLIM)
VSOM_SW: C26.2 L4.1 U13.1(SW)

Not connected (* = marked no-connect by the designer): P3 4(ID)*; P7 4(RSVD4)* 8(RSVD8)*; P8 1(WAKE#/MIC1P)* 3(COEX1/MIC1N)* 5(COEX2/EAR1P)* 6(+1.5V/NC)* 7(CLKREQ#/EAR1N)* 11(REFCLK-/UART_CTS)* 13(REFCLK+/UART_RTS)* 17(RSVD/UART_RXD)* 19(RSVD/UART_TXD)* 23(PER_N0/NC)* 25(PER_P0/NC)* 28(+1.5V/NC)* 30(GPIO9/SMB_CLK)* 31(PET_N0/NC)* 32(GPIO6/SMB_DATA)* 33(PET_P0/NC)* 42(LED_WWAN#)* 44(LED_WLAN#/UART_RI)* 45(RSVD/PCM_CLK)* 46(LED_WPAN#/UART_DTR)* 47(RSVD/PCM_OUT)* 48(+1.5V/NC)* 49(RSVD/PCM_IN)* 51(RSVD/PCM_SYNC)*; P11 8*; RN3 5(RD2)*; SP3 1*; SP4 1*; SP5 1*; SP6 1*; U10 35(CLKOUT)*; U40 1(RI)* 10(NC)* 11(GPIO3)* 12(GPIO2)* 13(GPIO1)* 14(GPIO0)* 15(SUSPEND#)* 17(SUSPEND)* 18(CTS)* 19(RTS)* 22(DSR)* 23(DTR)* 24(DCD)*; U41 3(IO2)* 5(VBUS)*; U42 4(IO3)*; U43 3(IO2)*

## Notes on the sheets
sheet 10
- CONFIG PINS
- Power-on Strapping Pins CFG
- RGMII Power Source
- CFG_EXT
- CFG_LDO[1:0]
- Enable internal delays
- CFG_EXT
- DNP
- External 3.3V (Default)
- 1
- 00
- DNP
- DNP
- TX delay is enabled
  RX delay is enabled
- CFG_LDO1
- External 1.8V
- 1
- 10
- CFG_LDO0
- Internal 1.8V
- 0
- 10
- PLLOFF
- TXDLY
- DNP
- RXDLY
- DNP
- DNP
- PHYADDRESS2
- PHYADDRESS1
- PHYADDRESS0
- DNP
- DNP
- PHY ADDRESS = [1,0,1]
- PHY support addresses from 00001 to 00111.
  PHY address 0 is a broadcast from the MAC
- PLLOFF: Pull-up to disable PLL @ ALDPS mode.
- Active low
- Active high
- Active low
- DNP
sheet 11
- Serial Console
- USB-to-Serial
- UART LEVEL SHIFTER
- Prevents power draining to board when only
  usb cable is connected
- DEBUG PORT
  (microUSB2.0 Type B)
  UART over USB
- A53 core debug
- USB console
  connection
  indicator
- In
- Out
- DNP
- JTAG
- NXP refdes layout
- Carrier board I2C
- TCK
- TMS
- GND
- VCC
- TDO
- GND
- TDI
- DNP
- DNP
- Micro-SD (bootable)
- DNP
- miniPCIe and SIM
- DNP
- DNP
- int. PU
- DNP
- EEPROM
- DNP
- DNP
- 3.3V x 2mA = 6.6mW
- I2C slave address: 0x54..0x57
- DNP
sheet 12
- Stitching capacitors
- For PCIe module
- Decoupling capacitors
- Through hole diameter should be 2.55mm
- For UCM-iMX93 module
- 12  Jumper Plugs
- For UCM-iMX93L module
sheet 13
- V_SOM (3A)
- Vout=3.7V
  Iout max = 3A
- Current measure
- DNP
- Vout=0.8*(1+64.9/17.8)=3.72V
- RLIM = 100k => ~4A
- VCC_3V3
- VCC_1V8
- Vout=0.8*(1+56.2/17.8)=3.33V
- Vout=0.8*(1+22.1/17.8)=1.79V
- Vout=3.3V
  Iout max = 3A
- Vout=1.8V
  Iout max = 3A
- RLIM = 100k => ~4A
- RLIM = 100k => ~4A
- DNP
- DNP
- VCC_5V
- PWR_CTRLn
- RTC battery
- Vout=5V
  Iout max = 3A
- Vout=0.8*(1+64.9/12.4)=4.987V
- DNP
- DNP
- RLIM = 100k => ~4A
- DNP
